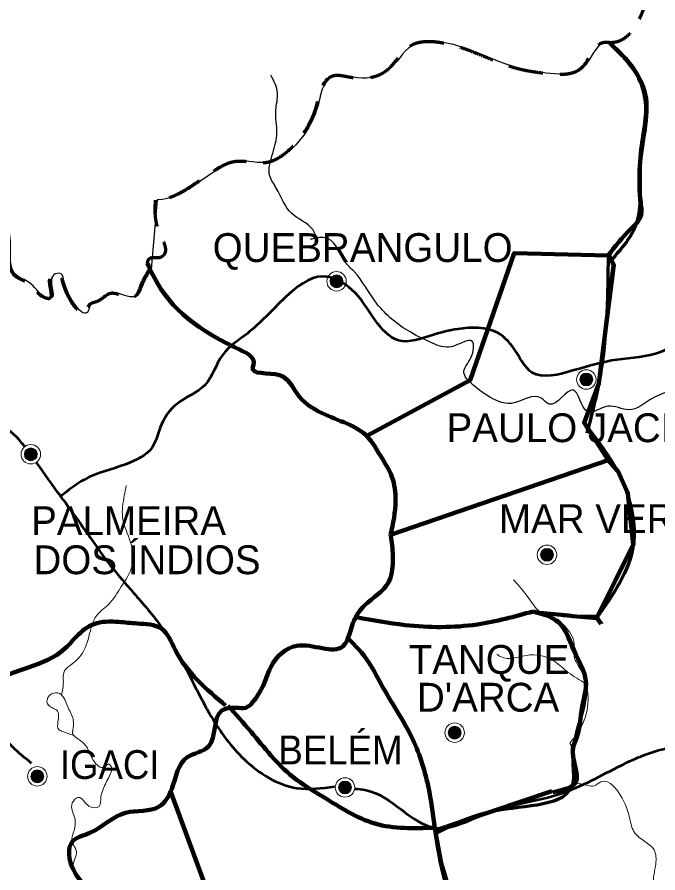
# Model space of a CAD drawing. Extents: x 512883 to 1063249, y 8784064 to 9081064.
# Drawn here: x 759622 to 792958, y 8936802 to 8981350 of the extents above; entities that cross this region are included whole.
import ezdxf

# ---------------------------------------------------------------- set-up
doc = ezdxf.new("R2010")
doc.units = 0
doc.header["$LTSCALE"] = 600
doc.linetypes.add('MEDIUM_DASHED', pattern=[4.5, 3, -1.5])
for name, color, linetype, lineweight in [('10', 7, 'Continuous', 53), ('13', 7, 'Continuous', 90), ('4', 7, 'Continuous', 13), ('5', 7, 'Continuous', 13), ('60', 7, 'Continuous', 25), ('9', 7, 'Continuous', 70)]:
    doc.layers.add(name, color=color, linetype=linetype, lineweight=lineweight)

msp = doc.modelspace()

# ---------------------------------------------------------------- linework, layer by layer
at = {"layer": '10'}
for points in [[(809616.9, 8959267.4), (809825.5, 8959797.2), (810249, 8961488.9), (810105.3, 8961759.7), (809170.8, 8962654), (807357.9, 8963023.8), (804970.4, 8962640.4), (803164.1, 8962405.1), (802121.3, 8962193), (800446.9, 8962751), (798563.3, 8964059.7), (797087.1, 8964868.8), (795673.1, 8965511.1), (794494.9, 8964818.7), (793098, 8963916.8), (790831.3, 8963513), (788586.3, 8962963.2), (786396.8, 8962851.7), (785601.5, 8963892.6), (784625.4, 8964912), (782553, 8965114), (781230, 8964796.7), (779464.4, 8964519.7), (778246.8, 8965580), (777043.4, 8967162.2), (775528.5, 8967845.9), (773570.9, 8966754.4), (771581.8, 8964869.9), (770307.8, 8963759.7), (769400.4, 8962212.5), (767924.2, 8961206.1), (767132.1, 8960139.2), (766642.8, 8958948.2), (765265.7, 8958067.2), (763103.9, 8957267.3), (761887.4, 8956407.7)], [(760025.4, 8958989.5), (758791.9, 8960070.6), (757224, 8960086.4), (755519.6, 8959726.1), (753291.3, 8959489.3), (750147.9, 8960209.6), (749997.5, 8960195.6)], [(760373.1, 8942504.5), (759520.9, 8943232.2), (758173.4, 8945126.8), (757857.6, 8946419.7), (757806.3, 8949236.7), (758306.2, 8953099), (758380.2, 8955499.1), (758834.8, 8958004.7), (759126.7, 8959859.4)], [(762022.2, 8956228.6), (761887.4, 8956407.7), (760623.2, 8958172.3)], [(762022.2, 8956228.6), (763065.5, 8954766.9), (764487.8, 8952789.5), (765663, 8951394.6), (767135.2, 8949600.3), (768531.3, 8947190.8), (769724.3, 8944935.2), (771450.3, 8942705.1), (774169.2, 8941219.5), (776144.1, 8941290.1)], [(777166.8, 8941184.2), (777784, 8941113.6), (781400.4, 8939142.2), (784141.8, 8939936.8), (787923.8, 8940936.4), (791046, 8942397.5), (793482.7, 8943294.7), (796021, 8942961.4), (797391.7, 8941602.9), (801402.2, 8942320.6), (803686.7, 8944268.7), (805438.1, 8945832.3), (806707.2, 8947652.2), (808027.2, 8948651.9), (817723.4, 8947344.6), (820490.2, 8947549.7), (822317.8, 8947447.2), (823942.3, 8946575.7), (825211.4, 8945755.4), (827474, 8943741.2), (830718.6, 8937881.3)]]:
    msp.add_spline(points, degree=3, dxfattribs=at)
at = {"layer": '13', "lineweight": 25}
msp.add_line((766913.4, 8971841.2), (766598, 8968225.6), dxfattribs=at)
at = {"layer": '13'}
msp.add_line((790366.5, 8958294.4), (779053.8, 8954397.2), dxfattribs=at)
for points in [[(790369.3, 8968937.3), (785483.9, 8969067.6), (783185.5, 8962444.9), (777810.8, 8959546.7)], [(790399.5, 8968972.9), (790656.5, 8968416.5), (789880.2, 8962278.7), (789119.1, 8960231.1), (790366.5, 8958294.4), (790875.4, 8957711.7), (791390.8, 8956544.8), (791681.4, 8953895.4), (789774.1, 8950070.4), (790016.3, 8949759.2)], [(785032.8, 8931732.7), (773881.6, 8927773.4), (773079.1, 8929461.1), (770243.9, 8933208.3), (769677, 8935397.6), (767593.6, 8941051.2)], [(787449.8, 8941056.1), (781374.7, 8939003.9), (781674.8, 8937314.5), (782217.5, 8935500.7), (782607.8, 8934729.8)]]:
    msp.add_lwpolyline(points, dxfattribs=at)
at = {"layer": '13', "lineweight": 25}
for points in [[(790107.8, 8949775.9), (789865.7, 8950087.1), (791772.9, 8953912.1), (791482.3, 8956561.5), (790967, 8957728.4), (790458, 8958311.1), (789210.6, 8960247.8), (789971.8, 8962295.4), (790748, 8968433.2), (790491.1, 8968989.6)], [(782699.4, 8934746.6), (782309, 8935517.4), (781766.3, 8937331.2), (781466.3, 8939020.6), (787541.4, 8941072.8)]]:
    msp.add_lwpolyline(points, dxfattribs=at)
at = {"layer": '13', "linetype": 'MEDIUM_DASHED', "lineweight": 70}
for points in [[(794561.3, 8984247.3), (793616.3, 8984286), (792392.4, 8982278.7), (790528.1, 8980018.9), (790126.1, 8980017.6), (788955.1, 8978678.2), (787269.9, 8978401.5), (785639, 8978667.5), (783741.9, 8979370.9), (781684.8, 8980011.2), (780098.6, 8979860), (778786.9, 8978520.2), (777001.7, 8978201.4), (775996.1, 8978260.7), (775361.7, 8977465.7), (775246.4, 8976985.3), (773727.5, 8974392.8), (772648.9, 8973784.1), (770940.2, 8973820.3), (769920, 8973378.8), (768383.8, 8972351.3), (766882.2, 8971824.7), (766821.9, 8971824.5)], [(753258.6, 8973800.6), (756145, 8972228.3), (758126.6, 8971149.5), (759060.8, 8970276.1), (759489.1, 8967898.4), (760156.5, 8967525), (761008.9, 8966776.5), (761311.1, 8966714.8), (761418.5, 8967904.7), (761819.8, 8967968.6), (761964.4, 8967614.3), (763228, 8966032.4), (763365, 8966366.7), (763825, 8966576.9), (764463.7, 8966975.4), (765249.4, 8966811), (765751.8, 8966812.7), (766047.5, 8967335.3), (766506.4, 8968208.9)], [(766401.5, 8968517.5), (766493.8, 8968776.7), (767015.7, 8968841), (767255.5, 8968966.9), (767000.5, 8970218.2), (766821.9, 8971824.5)]]:
    msp.add_spline(points, degree=3, dxfattribs=at)
at = {"layer": '13', "lineweight": 25}
for points in [[(790611.2, 8980028.3), (790217.7, 8980034.3), (789046.7, 8978694.9), (787361.4, 8978418.2), (785730.5, 8978684.2), (783833.4, 8979387.6), (781776.3, 8980027.9), (780190.2, 8979876.7), (778878.5, 8978536.9), (777093.2, 8978218.1), (776087.6, 8978277.4), (775453.3, 8977482.4), (775338, 8977002), (773819.1, 8974409.5), (772740.5, 8973800.8), (771031.7, 8973837), (770011.5, 8973395.5), (768475.3, 8972368), (766973.7, 8971841.4), (766913.4, 8971841.2)], [(790460.9, 8968954), (791631.4, 8970335.1), (792146.8, 8970983.6), (792137.3, 8971839.2), (792086.8, 8972778.1), (792188.4, 8974489.7), (792378.8, 8977265.8), (791780.2, 8978682.9), (790555.7, 8980005.8)], [(766598, 8968225.6), (766139.1, 8967352), (765843.4, 8966829.4), (765340.9, 8966827.7), (764555.2, 8966992.2), (763916.5, 8966593.6), (763456.6, 8966383.4), (763319.6, 8966049.1), (762055.9, 8967631), (761911.3, 8967985.3), (761510.1, 8967921.4), (761402.6, 8966731.5), (761100.5, 8966793.2), (760248, 8967541.7), (759580.7, 8967915.2), (759152.4, 8970292.8), (758218.2, 8971166.2), (756236.6, 8972245), (753350.1, 8973817.3)], [(787576.4, 8941019.1), (788774.3, 8941548.4), (788634.1, 8943321.8), (788809.5, 8943823.2), (789112.8, 8945472.7), (789299, 8946808.9), (788740.4, 8948247), (787858.2, 8949871.9), (786565.7, 8950431.2)]]:
    msp.add_spline(points, degree=3, dxfattribs=at)
at = {"layer": '13'}
for points in [[(790464.2, 8979989.1), (791688.7, 8978666.2), (792287.2, 8977249.1), (792096.9, 8974473), (791995.2, 8972761.4), (792045.8, 8971822.5), (792055.3, 8970966.9), (791539.9, 8970318.3), (790369.3, 8968937.3)], [(779053.8, 8954397.2), (779315.4, 8956192.7), (779120.9, 8957423.3), (778505.5, 8958548.2), (777872, 8959485.3), (775486.6, 8960729.7), (774168.7, 8961768.8), (773274, 8962705), (771882.4, 8963138.8), (771921.4, 8963243.2), (770966.7, 8964158.3), (766602, 8968088.4), (766401.5, 8968517.5)], [(762172.1, 8932529), (762915.7, 8932495.9), (762996.1, 8932496.2), (763331.1, 8933102.5), (763892.9, 8935003.3), (762565.1, 8936939.8), (762508.3, 8938442.1), (763407.8, 8938883.2), (765265.4, 8939932.7), (767010.5, 8940251.3), (767663.5, 8941171.6), (768469.3, 8942822.8), (769588.6, 8943389.9), (770271.4, 8945249.4), (771013.5, 8945397.9), (771515.9, 8945399.5), (771934, 8945755.6), (772466.8, 8946654.7), (772838.7, 8947553.2), (774173.5, 8948621.8), (776565.6, 8948587.8), (777094.8, 8949799.9), (777707.5, 8950740.9), (778940.6, 8951913.5), (779169.6, 8953020.3), (779097.1, 8954126.1), (779053.8, 8954397.2)], [(751215.9, 8950362.8), (753762, 8949641), (753762.7, 8949578.4), (755890.1, 8948041), (757527.9, 8947149), (757853, 8946837), (757993.7, 8946837.5), (759997, 8947428.2), (761876.7, 8948289.9), (763609.1, 8949756.3), (764914.3, 8949864.8), (765859.8, 8949784.4), (767129, 8949517.2), (767844.7, 8948413.5), (770470.8, 8945520.4)], [(786474.1, 8950414.5), (783567.3, 8949737.3), (779809.2, 8949704.3), (777285.7, 8950110.8)], [(787484.9, 8941002.4), (788682.8, 8941531.7), (788542.6, 8943305), (788717.9, 8943806.4), (789021.2, 8945456), (789207.5, 8946792.2), (788648.9, 8948230.3), (787766.7, 8949855.2), (786474.1, 8950414.5)], [(786606.8, 8950357.1), (788124.5, 8950211.1), (789774.1, 8950070.4)], [(781374.7, 8939003.9), (781071.2, 8941006.3), (780278.8, 8943591.4), (779355.7, 8945278.7), (778556.9, 8946632.6), (777921.4, 8947757.4), (776806.7, 8949056.3)], [(781351.7, 8939155.6), (778235.3, 8939369.4), (775546.8, 8940758.9), (773967.6, 8941797.2), (771791, 8944148.3), (770590.2, 8945500.8)]]:
    msp.add_spline(points, degree=3, dxfattribs=at)
at = {"layer": '4'}
msp.add_line((762549, 8943966.5), (762496.7, 8944081.9), dxfattribs=at)
at = {"layer": '4', "lineweight": 25}
for points in [[(775215.3, 8969867.5), (774999, 8970285.8), (773904.2, 8971137.9), (773105.9, 8972450), (772756.8, 8973116.6), (772925, 8974265), (773134.3, 8975329.9), (773081.2, 8976498.4), (773171.7, 8977396), (772819.7, 8978333.9)], [(818100.3, 8958307.5), (816732.1, 8958650.8), (814661, 8958727.6), (813018.1, 8958263.2), (811642.4, 8959072.6), (811814.1, 8959907.9), (811199.8, 8960928.5), (810644.2, 8962095.3), (809768.7, 8961299.5), (808746.2, 8961066.7), (807887.3, 8960583.9), (806988.5, 8960080.2), (805865.1, 8959888.7), (804485, 8961094.6), (803156.7, 8961257.3), (802496.5, 8960983.9), (800300.7, 8961435.9), (798890.6, 8961723.5), (797095.4, 8964117.5), (796246.2, 8964573.9), (795773.6, 8963695.9), (794965.5, 8962253.4), (793883.7, 8961936.8), (792702.5, 8961515.7), (791443, 8960906.4), (790355.7, 8961090.7), (789293.5, 8960816), (788537.4, 8961940.5), (787299.4, 8961206.1), (786894, 8961517.8), (785349.4, 8961241.5), (784078.6, 8961654.8), (783328.8, 8962215.8), (782859.3, 8962861.2), (783232.9, 8963613.7), (783283.5, 8964490.3), (782221.5, 8964194.7), (781234.7, 8964379.3), (780062.5, 8964959.8), (778358.1, 8966415.1), (777133.3, 8968122.4), (776706.2, 8968580.1), (775808.2, 8969808.4), (775064.4, 8969826.9), (774860.3, 8969768.4)]]:
    msp.add_spline(points, degree=3, dxfattribs=at)
at = {"layer": '4'}
for points in [[(761930.5, 8946052.6), (762027.4, 8946763.3), (762062.9, 8947262.6), (762482.1, 8947680), (763020.7, 8948243.3), (763432.6, 8949409.5), (763747.6, 8950180.1), (764386.5, 8950785.3), (765042.7, 8951702.7), (765596.6, 8952765.3), (765524.3, 8953992.4), (765108.6, 8955301.8), (765198.3, 8956446.2), (765294.1, 8956966.6)], [(788382.4, 8943559.9), (788892.7, 8944265.1), (789322.9, 8945618.6), (789296.2, 8946305), (788902.2, 8947447.9), (788614.9, 8947987.9), (788586.5, 8948840.8), (787952.4, 8949816.6), (787668.1, 8950044.6), (787365.2, 8950106), (786063.8, 8951329.5), (785452.2, 8952055.7)], [(789195.2, 8946661.8), (788299.8, 8947238.1), (787589.1, 8947797.6), (786316.2, 8948147.4), (784765.4, 8948059.5), (784582.8, 8948183.8)], [(762496.7, 8944081.9), (762529.7, 8944830.1), (762241.4, 8945474.1), (762096.9, 8945827.3), (761832, 8946138.6), (761409, 8946116.5), (761171.2, 8945699.7), (761456.3, 8945388.6), (761679.2, 8945264.4), (761745.5, 8944661.3), (761789.6, 8944266.2), (761992.1, 8944162.8), (762549, 8943966.5)], [(763934.9, 8930792.5), (763083.1, 8931351.6), (762836.9, 8931808.5), (762872.6, 8932287.1), (763246.6, 8933203.5), (763842.5, 8934099.8), (763914, 8935036.2), (763564.8, 8935721.6), (763341.4, 8935908.2), (762565.2, 8936987.6), (762581.1, 8937424.5), (762718.4, 8937820.1), (762470.1, 8938485.1), (762586, 8939005.5), (762620.1, 8939650.5), (762491.5, 8940440.6), (762811.1, 8940732.8), (763359.6, 8940276.8), (763883.7, 8940257.6), (763979.7, 8940757.2), (764096.7, 8941152.8), (764432.5, 8941861.1), (764508.4, 8942339.8), (764366.2, 8942464.2), (764166.1, 8942317.9), (763578.3, 8942669.8), (763167.7, 8943459.1), (762741.1, 8943811.4), (762496.7, 8944081.1), (762495.9, 8944164.3)], [(830241.8, 8913061.2), (829149, 8913536.4), (827439.7, 8913177.5), (826147.8, 8913402.5), (825384.3, 8913171.3), (824554.1, 8913584.9), (823759.2, 8914518.6), (822827.3, 8915035.8), (821955, 8915636.5), (821248.5, 8915759.2), (819586.9, 8916711.1), (818533.7, 8917269.5), (817362.3, 8917536.4), (815944.8, 8918260.2), (814975.2, 8918506.9), (813404.4, 8918398.2), (812633.1, 8918978.3), (812224, 8919601.2), (811906.3, 8921202), (811391.5, 8922344.6), (811100.9, 8923217.4), (810271.4, 8923568.6), (809585.4, 8923649.7), (808316.8, 8923562.7), (807869.8, 8923935.8), (806863.7, 8923787.1), (805966.1, 8924928.5), (805085.5, 8926382.1), (804213.4, 8926961.9), (803507.4, 8927043), (803043.7, 8927062.4), (801988.8, 8925707), (801265.4, 8925496.8), (800038, 8925305.8), (799427.5, 8925928.1), (797719, 8927566.3), (796560.5, 8928582.1), (796030.6, 8929204.6), (795985.9, 8929662.2), (795818.1, 8930348.1), (794959.1, 8931656.1), (795129.4, 8932800.8), (795079.4, 8933799.2), (794428.2, 8934462.9), (793375.3, 8934979.8), (792885.7, 8935602.4), (792718.7, 8936205.2), (792849.5, 8937266.5), (792761.8, 8937994.3), (791766, 8938865), (791496.6, 8939633.9), (791206.3, 8940486), (789987, 8941543.2), (789646.5, 8941334.2), (788960.3, 8941436.1), (788819.1, 8941456.5), (788590.6, 8942163.1), (788458, 8943369.2), (788382.4, 8943559.9)]]:
    msp.add_spline(points, degree=3, dxfattribs=at)
at = {"layer": '5'}
for p, q in [((775910.6, 8967637.6), (776571.2, 8967637.6)), ((775915.3, 8967667.6), (776566.3, 8967667.6)), ((775923.5, 8967697.6), (776558.2, 8967697.6)), ((775934.2, 8967727.6), (776547.5, 8967727.9)), ((775948.7, 8967757.6), (776533.3, 8967757.6)), ((775967, 8967787.6), (776515.1, 8967787.6)), ((775991, 8967817.6), (776491.3, 8967817.6)), ((776020.1, 8967847.6), (776461.7, 8967847.6)), ((776059.7, 8967877.6), (776422.1, 8967877.6)), ((776117, 8967907.6), (776364.8, 8967907.6)), ((775908.5, 8967607.6), (776573.2, 8967607.6)), ((775909.1, 8967577.6), (776573, 8967577.6)), ((775912.1, 8967547.6), (776569.7, 8967547.6)), ((775918.1, 8967517.6), (776563.7, 8967517.6)), ((775927.1, 8967487.6), (776554.7, 8967487.6)), ((775939.7, 8967457.6), (776542.3, 8967457.9)), ((775955.6, 8967427.6), (776526.2, 8967427.6)), ((775976.2, 8967397.6), (776505.8, 8967397.9)), ((776001.5, 8967367.3), (776480.6, 8967367.6)), ((776034.8, 8967337.6), (776447, 8967337.6)), ((776079.8, 8967307.6), (776402, 8967307.6)), ((776153.6, 8967277.6), (776327.8, 8967277.6)), ((789016.7, 8962735.8), (789458.3, 8962735.8)), ((789056.3, 8962765.8), (789418.7, 8962765.8)), ((789113.6, 8962795.8), (789361.4, 8962795.8)), ((788905.1, 8962495.8), (789569.9, 8962495.8)), ((788905.7, 8962465.8), (789569.6, 8962465.8)), ((788907.2, 8962525.8), (789567.8, 8962525.8)), ((788908.7, 8962435.8), (789566.3, 8962435.8)), ((788912, 8962555.8), (789563, 8962555.8)), ((788914.7, 8962405.8), (789560.3, 8962405.8)), ((788920.1, 8962585.8), (789554.9, 8962585.8)), ((788923.7, 8962375.8), (789551.3, 8962375.8)), ((788930.9, 8962615.8), (789544.1, 8962616.1)), ((788936.3, 8962345.8), (789539, 8962346.1)), ((788945.3, 8962645.8), (789530, 8962645.8)), ((788952.2, 8962315.8), (789522.8, 8962315.8)), ((788963.6, 8962675.8), (789511.7, 8962675.8)), ((788972.9, 8962285.8), (789502.4, 8962286.1)), ((788987.6, 8962705.8), (789488, 8962705.8)), ((788998.1, 8962255.5), (789477.2, 8962255.8)), ((789031.4, 8962225.8), (789443.6, 8962225.8)), ((789076.4, 8962195.8), (789398.6, 8962195.8)), ((789150.2, 8962165.8), (789324.5, 8962165.8)), ((760028.4, 8958722.3), (760641.6, 8958722.6)), ((760042.8, 8958752.3), (760627.5, 8958752.3)), ((760061.1, 8958782.3), (760609.2, 8958782.3)), ((760085.1, 8958812.3), (760585.5, 8958812.3)), ((760114.2, 8958842.3), (760555.8, 8958842.3)), ((760153.8, 8958872.3), (760516.2, 8958872.3)), ((760211.1, 8958902.3), (760458.9, 8958902.3)), ((760002.6, 8958602.3), (760667.4, 8958602.3)), ((760003.2, 8958572.3), (760667.1, 8958572.3)), ((760004.7, 8958632.3), (760665.3, 8958632.3)), ((760006.2, 8958542.3), (760663.8, 8958542.3)), ((760009.5, 8958662.3), (760660.5, 8958662.3)), ((760012.2, 8958512.3), (760657.8, 8958512.3)), ((760017.6, 8958692.3), (760652.4, 8958692.3)), ((760021.2, 8958482.3), (760648.8, 8958482.3)), ((760033.8, 8958452.3), (760636.5, 8958452.6)), ((760049.7, 8958422.3), (760620.3, 8958422.3)), ((760070.4, 8958392.3), (760599.9, 8958392.6)), ((760095.6, 8958362), (760574.7, 8958362.3)), ((760128.9, 8958332.3), (760541.1, 8958332.3)), ((760173.9, 8958302.3), (760496.1, 8958302.3)), ((760247.7, 8958272.3), (760422, 8958272.3)), ((786855.5, 8953369.7), (787520.3, 8953369.7)), ((786857.6, 8953399.7), (787518.2, 8953399.7)), ((786862.4, 8953429.7), (787513.4, 8953429.7)), ((786870.5, 8953459.7), (787505.3, 8953459.7)), ((786881.3, 8953489.7), (787494.5, 8953490)), ((786895.7, 8953519.7), (787480.4, 8953519.7)), ((786914, 8953549.7), (787462.1, 8953549.7)), ((786938, 8953579.7), (787438.4, 8953579.7)), ((786967.1, 8953609.7), (787408.7, 8953609.7)), ((787006.7, 8953639.7), (787369.1, 8953639.7)), ((787064, 8953669.7), (787311.8, 8953669.7)), ((786856.1, 8953339.7), (787520, 8953339.7)), ((786859.1, 8953309.7), (787516.7, 8953309.7)), ((786865.1, 8953279.7), (787510.7, 8953279.7)), ((786874.1, 8953249.7), (787501.7, 8953249.7)), ((786886.7, 8953219.7), (787489.4, 8953220)), ((786902.6, 8953189.7), (787473.2, 8953189.7)), ((786923.3, 8953159.7), (787452.8, 8953160)), ((786948.5, 8953129.4), (787427.6, 8953129.7)), ((786981.8, 8953099.7), (787394, 8953099.7)), ((787026.8, 8953069.7), (787349, 8953069.7)), ((787100.6, 8953039.7), (787274.9, 8953039.7)), ((782053.9, 8944109.5), (782718.7, 8944109.5)), ((782054.5, 8944079.5), (782718.4, 8944079.5)), ((782056, 8944139.5), (782716.6, 8944139.5)), ((782057.5, 8944049.5), (782715.1, 8944049.5)), ((782060.8, 8944169.5), (782711.8, 8944169.5)), ((782063.5, 8944019.5), (782709.1, 8944019.5)), ((782068.9, 8944199.5), (782703.7, 8944199.5)), ((782079.7, 8944229.5), (782692.9, 8944229.8)), ((782094.1, 8944259.5), (782678.8, 8944259.5)), ((782112.4, 8944289.5), (782660.5, 8944289.5)), ((782136.4, 8944319.5), (782636.8, 8944319.5)), ((782165.5, 8944349.5), (782607.1, 8944349.5)), ((782205.1, 8944379.5), (782567.5, 8944379.5)), ((782262.4, 8944409.5), (782510.2, 8944409.5)), ((782072.5, 8943989.5), (782700.1, 8943989.5)), ((782085.1, 8943959.5), (782687.8, 8943959.8)), ((782101, 8943929.5), (782671.6, 8943929.5)), ((782121.7, 8943899.5), (782651.2, 8943899.8)), ((782146.9, 8943869.2), (782626, 8943869.5)), ((782180.2, 8943839.5), (782592.4, 8943839.5)), ((782225.2, 8943809.5), (782547.4, 8943809.5)), ((782299, 8943779.5), (782473.3, 8943779.5)), ((760341, 8941836.9), (761005.8, 8941836.9)), ((760341.6, 8941806.9), (761005.5, 8941806.9)), ((760343.1, 8941866.9), (761003.7, 8941866.9)), ((760347.9, 8941896.9), (760998.9, 8941896.9)), ((760356, 8941926.9), (760990.8, 8941926.9)), ((760366.8, 8941956.9), (760980, 8941957.2)), ((760381.2, 8941986.9), (760965.9, 8941986.9)), ((760399.5, 8942016.9), (760947.6, 8942016.9)), ((760423.5, 8942046.9), (760923.9, 8942046.9)), ((760452.6, 8942076.9), (760894.2, 8942076.9)), ((760492.2, 8942106.9), (760854.6, 8942106.9)), ((760549.5, 8942136.9), (760797.3, 8942136.9)), ((760344.6, 8941776.9), (761002.2, 8941776.9)), ((760350.6, 8941746.9), (760996.2, 8941746.9)), ((760359.6, 8941716.9), (760987.2, 8941716.9)), ((760372.2, 8941686.9), (760974.9, 8941687.2)), ((760388.1, 8941656.9), (760958.7, 8941656.9)), ((760408.8, 8941626.9), (760938.3, 8941627.2)), ((760434, 8941596.6), (760913.1, 8941596.9)), ((760467.3, 8941566.9), (760879.5, 8941566.9)), ((760512.3, 8941536.9), (760834.5, 8941536.9)), ((760586.1, 8941506.9), (760760.4, 8941506.9)), ((776362.7, 8941347), (776997.5, 8941347)), ((776373.5, 8941377), (776986.7, 8941377.3)), ((776387.9, 8941407), (776972.6, 8941407)), ((776406.2, 8941437), (776954.3, 8941437)), ((776430.2, 8941467), (776930.6, 8941467)), ((776459.3, 8941497), (776900.9, 8941497)), ((776498.9, 8941527), (776861.3, 8941527)), ((776556.2, 8941557), (776804, 8941557)), ((776347.7, 8941257), (777012.5, 8941257)), ((776348.3, 8941227), (777012.2, 8941227)), ((776349.8, 8941287), (777010.4, 8941287)), ((776351.3, 8941197), (777008.9, 8941197)), ((776354.6, 8941317), (777005.6, 8941317)), ((776357.3, 8941167), (777002.9, 8941167)), ((776366.3, 8941137), (776993.9, 8941137)), ((776378.9, 8941107), (776981.6, 8941107.3)), ((776394.8, 8941077), (776965.4, 8941077)), ((776415.5, 8941047), (776945, 8941047.3)), ((776440.7, 8941016.7), (776919.8, 8941017)), ((776474, 8940987), (776886.2, 8940987)), ((776519, 8940957), (776841.2, 8940957)), ((776592.8, 8940927), (776767.1, 8940927))]:
    msp.add_line(p, q, dxfattribs=at)
for centre, radius in [((776240.9, 8967598.6), 506.1), ((776240.9, 8967598.6), 332.9), ((789237.6, 8962486.8), 506.1), ((789237.6, 8962486.8), 332.9), ((760335.1, 8958593.3), 506.1), ((760335.1, 8958593.3), 332.9), ((787188, 8953360.7), 506.1), ((787188, 8953360.7), 332.9), ((782386.4, 8944100.5), 506.1), ((782386.4, 8944100.5), 332.9), ((760673.5, 8941827.9), 506.1), ((760673.5, 8941827.9), 332.9), ((776680.2, 8941248), 506.1), ((776680.2, 8941248), 332.9)]:
    msp.add_circle(centre, radius, dxfattribs=at)
at = {"layer": '60'}
msp.add_spline([(928828.8, 9027989.5), (927727.3, 9017705.9), (905698.2, 8975836.8), (863108.4, 8926255), (823455.9, 8876673.2), (798489.5, 8846556.8), (787107.7, 8828193.2)], degree=3, dxfattribs=at)
msp.add_spline([(928828.8, 9027989.5), (927727.3, 9017705.9), (905698.2, 8975836.8), (863108.4, 8926255), (823455.9, 8876673.2), (798489.5, 8846556.8), (787107.7, 8828193.2)], degree=3, dxfattribs=at)
at = {"layer": '9'}
for points in [[(790535.2, 8979912.3), (792268.9, 8977558.3), (792052.8, 8973793.7), (792032.4, 8972025.7), (791847.4, 8970645.6), (790528, 8968694.7)], [(790369.3, 8968937.3), (790268.4, 8965347.6), (789880.2, 8962278.7), (789258.9, 8959684.3)], [(789119.1, 8960231.1), (791133.1, 8957128.2), (791681.4, 8953895.4), (789774.1, 8950070.4)], [(781383.8, 8938829.6), (784412.3, 8940030), (788542.7, 8941469.8), (788543.9, 8942727.5), (788863.5, 8944569), (789201.8, 8946908.8), (788671.4, 8948289.4), (787820.1, 8949815.2), (786474.1, 8950414.5)], [(786474.1, 8950414.5), (788245.7, 8950187.8), (789821.8, 8950166)], [(792238.3, 8921764.6), (791503.1, 8924017.9), (791016, 8925049.1), (788389.3, 8925758.2), (788303.5, 8926642.7), (787188.2, 8929831.3), (784783.9, 8932224.2), (782217.5, 8935500.7), (781373.7, 8938939.8)]]:
    msp.add_spline(points, degree=3, dxfattribs=at)

# ---------------------------------------------------------------- texts
at = {"layer": '5'}
for s, p in [('QUEBRANGULO', (769796.3, 8968604)), ('PAULO JACINTO', (781961.8, 8959223.7)), ('PALMEIRA ', (760348.3, 8954385.5)), ('MAR VERMELHO', (784687.5, 8954491.6)), ('DOS ÍNDIOS', (760473.3, 8952351.3)), ('TANQUE', (779996.1, 8947163.8)), ("D'ARCA", (780423.7, 8945196.1))]:
    msp.add_text(s, height=1500, dxfattribs=at).set_placement(p)
at = {"layer": '5', "width": 0.95}
for s, p in [('BELÉM', (773216, 8942450.8)), ('IGACI', (761842.2, 8941689.9))]:
    msp.add_text(s, height=1500, dxfattribs=at).set_placement(p)

doc.saveas('drawing.dxf')
